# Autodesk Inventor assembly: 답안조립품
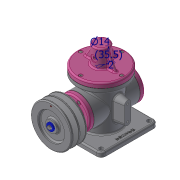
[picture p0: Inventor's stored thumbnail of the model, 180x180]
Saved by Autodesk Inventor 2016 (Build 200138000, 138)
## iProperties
Created: 2020-02
Part Number: 답안조립품
Material: 일반
Document SubType Name: Assembly
Designer: Administrator
Author: Administrator
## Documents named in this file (21)
- C:\Users\Administrator\Desktop\600206V1012\답안조립품.iam
- C:\Users\Administrator\Desktop\600206V1012\본체.ipt
- C:\Users\Administrator\Desktop\600206V1012\볼트 M4 x 10.ipt
- C:\Users\Administrator\Desktop\600206V1012\슬라이더.ipt
- C:\Users\Administrator\Desktop\600206V1012\앞커버.ipt
- C:\Users\Administrator\Desktop\600206V1012\오일 실 17 30 8.ipt
- C:\Users\Administrator\Desktop\600206V1012\와셔 4x16.ipt
- C:\Users\Administrator\Desktop\600206V1012\육각 소켓 머리 볼트 M4 x 10.ipt
- C:\Users\Administrator\Desktop\600206V1012\클레비스 핀 6 x 22.ipt
- 클레비스 핀 6 x 22.ipt
- C:\Users\Administrator\Desktop\600206V1012\키 4 x 4 x 25.ipt
- C:\Users\Administrator\Desktop\600206V1012\편심축.ipt
- C:\Users\Administrator\Desktop\600206V1012\E-링.ipt
- C:\Users\Administrator\Desktop\600206V1012\V-벨트풀리.ipt
- C:\Users\Administrator\Desktop\600206V1012\가변스프링.ipt
- C:\Users\Administrator\Desktop\600206V1012\개스킷 A.ipt
- C:\Users\Administrator\Desktop\600206V1012\개스킷 B.ipt
- C:\Users\Administrator\Desktop\600206V1012\덮개.ipt
- C:\Users\Administrator\Desktop\600206V1012\뒤커버.ipt
- C:\Users\Administrator\Desktop\600206V1012\링크.ipt
- C:\Users\Administrator\Desktop\600206V1012\베어링 17 x 40 x 12.ipt
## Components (6 placed, 5 different names)
1. E-링:1
2. V-벨트풀리:1 — 각도:2, 플러쉬:1
3. 가변스프링:1
4. 개스킷 A:1
5. 개스킷 B:1
6. 개스킷 A:2
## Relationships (2: Angle 1, Flush 1)
- 각도:2 [Angle]: V-벨트풀리:1
- 플러쉬:1 [Flush]: V-벨트풀리:1
